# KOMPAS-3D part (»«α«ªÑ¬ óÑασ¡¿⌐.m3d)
File: created 20.08.2015 19:35:12, last saved 22.07.2016 16:39:13.
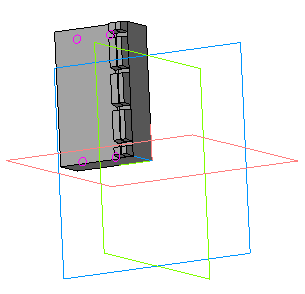
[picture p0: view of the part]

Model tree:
1. Эскиз:1
2. Операция выдавливания:1
     Расстояние 1 = 8
3. Эскиз:2
4. Операция выдавливания:2
     Расстояние 1 = 1
5. Эскиз:3
6. Операция выдавливания:3
     Расстояние 1 = 2.5; Угол 1 = 8
7. Эскиз:4
8. Вырезать элемент выдавливания:1
     Расстояние 1 = 20
9. Эскиз:5
10. Вырезать элемент выдавливания:2
     Расстояние 1 = 3; Угол 1 = 19
11. Скругление:1
     Радиус = 1
12. Скругление:2
     Радиус = 1
13. Скругление:3
     Радиус = 1
14. Эскиз:6
15. Эскиз:7
16. Вырезать элемент выдавливания:3
     Расстояние 1 = 2.5
17. Эскиз:8
18. Вырезать элемент выдавливания:4
     Расстояние 1 = 42
19. Операция выдавливания:4
     Расстояние 1 = 0.8; Расстояние 2 = 1.5
20. Эскиз:9
21. Вырезать элемент выдавливания:5
     Расстояние 1 = 30
22. Эскиз:10
23. Вырезать элемент выдавливания:6
     Расстояние 1 = 10
24. Эскиз:11
25. Операция выдавливания:5
     Расстояние 1 = 3
26. Эскиз:12
27. Вырезать элемент выдавливания:7
     Толщина стенки 1 = 0.2; Расстояние 1 = 2.5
